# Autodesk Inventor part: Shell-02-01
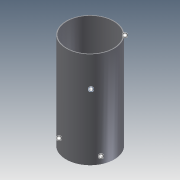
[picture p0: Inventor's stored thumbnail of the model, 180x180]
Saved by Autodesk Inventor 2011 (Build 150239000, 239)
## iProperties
Created: 2010-06
Part Number: Shell-02-01
Document SubType Name: Modeling
Designer: mklassen
Density: 1 g/cm^3
OD: 36.000 in
THK: 0.625 in
LEN: 6.000 ft
SKVOFS: 6.000 in
Author: mklassen
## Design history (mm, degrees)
sketch "skShell"
  geometry: C1 r 457.2 at (0, 0); C2 r 441.325 at (0, 0); 1 further point
  constraints: 2 centre point, 1 coincident
  dimensions: "d0" = 914.4 diameter of C1 (derived); "d1" = 15.875 radial gap between concentric circles of C2 C1 (derived)
extrude "Shell" new body sketch "skShell" stored distance "d2" = 1828.8 (derived); taper "d3" = 0 deg
body "Solid1"
other parameters: "d4" = 0, "d5" = 0, "d6" = 0, "d8" = 0, "SKVOFS" = 152.4 [user parameter], "d9" = 0
